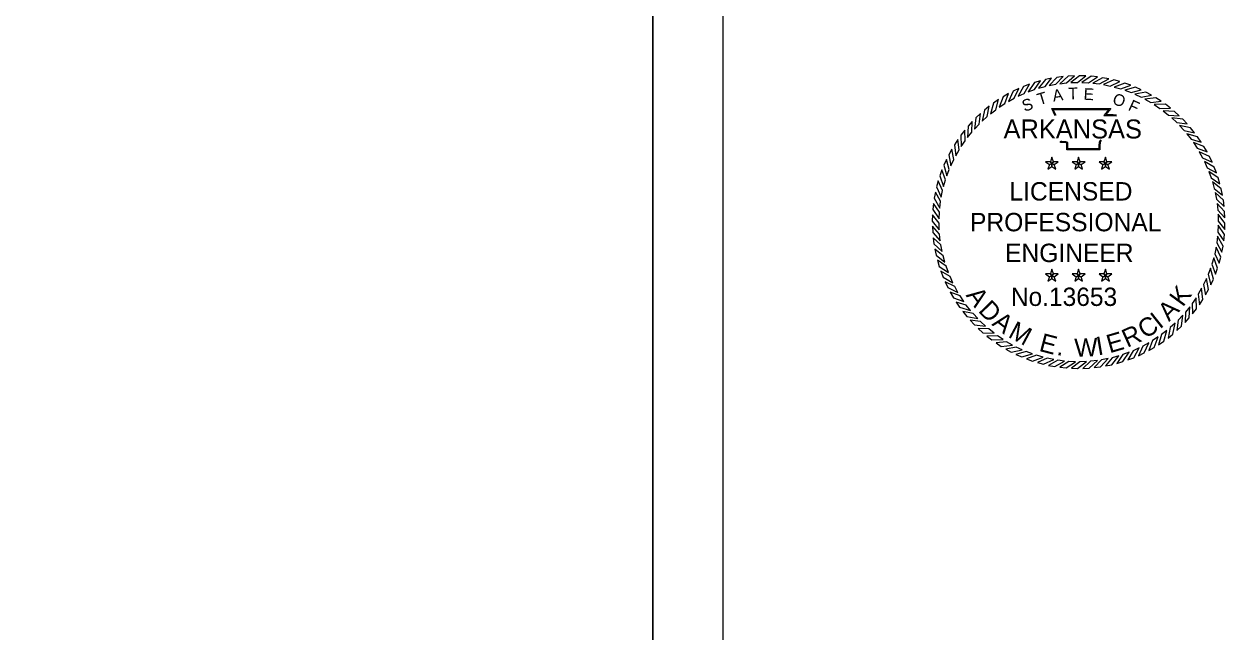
# Model space of a CAD drawing. Extents: x 0 to 38.1, y -1.4 to 22.
# Drawn here: x 28.28 to 38.1, y 10.32 to 15.29 of the extents above; entities that cross this region are included whole.
import ezdxf

# ---------------------------------------------------------------- set-up
doc = ezdxf.new("R2010")
doc.units = 0
doc.layers.add('1', color=7, linetype='Continuous')
doc.layers.add('G-ANNO-STMP-AEW', color=7, linetype='Continuous')

msp = doc.modelspace()

# ---------------------------------------------------------------- linework, layer by layer
at = {"layer": '1'}
msp.add_line((33.4232, 0.5768), (33.4232, 21.4232), dxfattribs=at)
for points in [[(34, 22), (0, 22), (0, 0), (34, 0)], [(1.516, 0.5768), (1.516, 21.4232), (25.1972, 21.4232), (25.1972, 20.4352), (29.1132, 20.4352), (29.1132, 20.1432), (33.4232, 20.1432), (33.4232, 0.5768)]]:
    msp.add_lwpolyline(points, close=True, dxfattribs=at)
at = {"layer": 'G-ANNO-STMP-AEW'}
for points in [[(36.5929, 14.8264), (36.5435, 14.8119), (36.4922, 14.7359), (36.5445, 14.7547)], [(36.6844, 14.8473), (36.6341, 14.8368), (36.577, 14.765), (36.6306, 14.7797)], [(36.7774, 14.861), (36.7263, 14.8544), (36.6638, 14.7874), (36.7184, 14.7978)], [(36.8711, 14.8674), (36.8197, 14.8648), (36.7521, 14.8029), (36.8073, 14.809)], [(36.965, 14.8664), (36.9136, 14.8679), (36.8413, 14.8114), (36.8969, 14.8132)], [(37.0586, 14.858), (37.0074, 14.8635), (36.931, 14.8129), (36.9865, 14.8103)], [(37.1512, 14.8423), (37.1006, 14.8518), (37.0204, 14.8074), (37.0756, 14.8004)], [(37.2423, 14.8194), (37.1926, 14.8329), (37.1092, 14.7949), (37.1636, 14.7836)], [(36.4161, 14.7633), (36.3696, 14.7413), (36.3308, 14.6582), (36.3795, 14.6849)], [(36.5032, 14.7983), (36.4552, 14.78), (36.41, 14.7002), (36.4607, 14.7231)], [(37.3313, 14.7895), (37.2828, 14.8067), (37.1967, 14.7754), (37.2501, 14.7599)], [(37.4177, 14.7526), (37.3707, 14.7736), (37.2824, 14.7491), (37.3344, 14.7295)], [(37.5009, 14.7091), (37.4558, 14.7337), (37.3658, 14.7162), (37.4161, 14.6926)], [(36.2513, 14.6733), (36.2088, 14.6443), (36.1836, 14.5561), (36.2275, 14.5902)], [(36.3319, 14.7216), (36.2873, 14.6959), (36.2552, 14.61), (36.3016, 14.6406)], [(37.5805, 14.6591), (37.5374, 14.6872), (37.4463, 14.6769), (37.4946, 14.6493)], [(37.6559, 14.6031), (37.6151, 14.6345), (37.5235, 14.6313), (37.5695, 14.6001)], [(36.1027, 14.5587), (36.0653, 14.5234), (36.0541, 14.4324), (36.0921, 14.4729)], [(36.1747, 14.6189), (36.1347, 14.5866), (36.1164, 14.4968), (36.1575, 14.5342)], [(37.7267, 14.5413), (37.6885, 14.5759), (37.5969, 14.5798), (37.6403, 14.5451)], [(36.0355, 14.493), (36.001, 14.4548), (35.997, 14.3632), (36.0318, 14.4066)], [(37.7924, 14.4742), (37.757, 14.5116), (37.666, 14.5228), (37.7066, 14.4847)], [(37.8526, 14.4021), (37.8203, 14.4422), (37.7305, 14.4605), (37.7679, 14.4194)], [(35.9177, 14.3468), (35.8896, 14.3037), (35.9, 14.2126), (35.9275, 14.2609)], [(35.9738, 14.4222), (35.9424, 14.3815), (35.9456, 14.2898), (35.9768, 14.3358)], [(37.907, 14.3256), (37.878, 14.368), (37.7898, 14.3933), (37.8239, 14.3494)], [(35.8678, 14.2673), (35.8432, 14.2221), (35.8607, 14.1321), (35.8843, 14.1824)], [(37.9552, 14.2449), (37.9296, 14.2896), (37.8437, 14.3217), (37.8742, 14.2752)], [(37.997, 14.1608), (37.9749, 14.2073), (37.8918, 14.246), (37.9186, 14.1973)], [(35.8243, 14.184), (35.8032, 14.1371), (35.8277, 14.0487), (35.8474, 14.1007)], [(36.6865, 14.148), (36.6742, 14.1649), (36.6345, 14.1649), (36.6667, 14.1415)], [(36.6865, 14.148), (36.6667, 14.1415), (36.6544, 14.1037), (36.6865, 14.1271)], [(36.6865, 14.148), (36.6988, 14.1649), (36.6865, 14.2027), (36.6742, 14.1649)], [(36.6865, 14.148), (36.7064, 14.1415), (36.7385, 14.1649), (36.6988, 14.1649)], [(36.6865, 14.148), (36.6865, 14.1271), (36.7187, 14.1037), (36.7064, 14.1415)], [(36.9053, 14.148), (36.893, 14.1649), (36.8533, 14.1649), (36.8854, 14.1415)], [(36.9053, 14.148), (36.8854, 14.1415), (36.8731, 14.1037), (36.9053, 14.1271)], [(36.9053, 14.148), (36.9175, 14.1649), (36.9053, 14.2027), (36.893, 14.1649)], [(36.9053, 14.148), (36.9251, 14.1415), (36.9573, 14.1649), (36.9175, 14.1649)], [(36.9053, 14.148), (36.9053, 14.1271), (36.9374, 14.1037), (36.9251, 14.1415)], [(37.124, 14.148), (37.1117, 14.1649), (37.072, 14.1649), (37.1042, 14.1415)], [(37.124, 14.148), (37.1042, 14.1415), (37.0919, 14.1037), (37.124, 14.1271)], [(37.124, 14.148), (37.1363, 14.1649), (37.124, 14.2027), (37.1117, 14.1649)], [(37.124, 14.148), (37.1439, 14.1415), (37.176, 14.1649), (37.1363, 14.1649)], [(37.124, 14.148), (37.124, 14.1271), (37.1562, 14.1037), (37.1439, 14.1415)], [(38.032, 14.0736), (38.0137, 14.1217), (37.9339, 14.1669), (37.9567, 14.1162)], [(35.7874, 14.0976), (35.7701, 14.0492), (35.8015, 13.963), (35.817, 14.0164)], [(38.0601, 13.984), (38.0456, 14.0334), (37.9695, 14.0846), (37.9884, 14.0323)], [(35.7574, 14.0086), (35.744, 13.9589), (35.782, 13.8755), (35.7933, 13.9299)], [(38.081, 13.8924), (38.0704, 13.9428), (37.9987, 13.9999), (38.0133, 13.9463)], [(35.7345, 13.9175), (35.725, 13.8669), (35.7695, 13.7868), (35.7764, 13.8419)], [(38.0947, 13.7995), (38.0881, 13.8505), (38.0211, 13.9131), (38.0315, 13.8585)], [(35.7188, 13.8249), (35.7133, 13.7737), (35.7639, 13.6973), (35.7665, 13.7528)], [(38.1011, 13.7058), (38.0985, 13.7572), (38.0366, 13.8248), (38.0427, 13.7695)], [(35.7105, 13.7313), (35.709, 13.6799), (35.7655, 13.6077), (35.7637, 13.6632)], [(38.1001, 13.6119), (38.1015, 13.6633), (38.0451, 13.7355), (38.0468, 13.68)], [(35.7095, 13.6374), (35.712, 13.586), (35.774, 13.5184), (35.7679, 13.5737)], [(38.076, 13.4257), (38.0855, 13.4762), (38.0411, 13.5564), (38.0341, 13.5013)], [(38.0917, 13.5183), (38.0972, 13.5695), (38.0466, 13.6459), (38.044, 13.5904)], [(35.7158, 13.5437), (35.7224, 13.4927), (35.7895, 13.4301), (35.7791, 13.4847)], [(35.7295, 13.4508), (35.7401, 13.4004), (35.8119, 13.3433), (35.7972, 13.3969)], [(38.0531, 13.3346), (38.0665, 13.3843), (38.0285, 13.4677), (38.0173, 13.4133)], [(35.7505, 13.3592), (35.765, 13.3098), (35.841, 13.2586), (35.8222, 13.3109)], [(38.0231, 13.2456), (38.0404, 13.294), (38.0091, 13.3802), (37.9936, 13.3268)], [(35.7786, 13.2696), (35.7969, 13.2215), (35.8767, 13.1763), (35.8538, 13.227)], [(36.6865, 13.2319), (36.6988, 13.2488), (36.6865, 13.2866), (36.6742, 13.2488)], [(36.9053, 13.2319), (36.9175, 13.2488), (36.9053, 13.2866), (36.893, 13.2488)], [(37.124, 13.2319), (37.1363, 13.2488), (37.124, 13.2866), (37.1117, 13.2488)], [(37.9863, 13.1592), (38.0073, 13.2061), (37.9828, 13.2945), (37.9632, 13.2425)], [(35.8136, 13.1824), (35.8356, 13.1359), (35.9187, 13.0972), (35.8919, 13.1459)], [(36.6865, 13.2319), (36.6742, 13.2488), (36.6345, 13.2488), (36.6667, 13.2255)], [(36.6865, 13.2319), (36.6667, 13.2255), (36.6544, 13.1877), (36.6865, 13.2111)], [(36.6865, 13.2319), (36.7064, 13.2255), (36.7385, 13.2488), (36.6988, 13.2488)], [(36.6865, 13.2319), (36.6865, 13.2111), (36.7187, 13.1877), (36.7064, 13.2255)], [(36.9053, 13.2319), (36.893, 13.2488), (36.8533, 13.2488), (36.8854, 13.2255)], [(36.9053, 13.2319), (36.8854, 13.2255), (36.8731, 13.1877), (36.9053, 13.2111)], [(36.9053, 13.2319), (36.9251, 13.2255), (36.9573, 13.2488), (36.9175, 13.2488)], [(36.9053, 13.2319), (36.9053, 13.2111), (36.9374, 13.1877), (36.9251, 13.2255)], [(37.124, 13.2319), (37.1117, 13.2488), (37.072, 13.2488), (37.1042, 13.2255)], [(37.124, 13.2319), (37.1042, 13.2255), (37.0919, 13.1877), (37.124, 13.2111)], [(37.124, 13.2319), (37.1439, 13.2255), (37.176, 13.2488), (37.1363, 13.2488)], [(37.124, 13.2319), (37.124, 13.2111), (37.1562, 13.1877), (37.1439, 13.2255)], [(37.9427, 13.0759), (37.9674, 13.1211), (37.9499, 13.2111), (37.9262, 13.1608)], [(35.8553, 13.0982), (35.8809, 13.0536), (35.9668, 13.0215), (35.9363, 13.068)], [(37.8928, 12.9964), (37.9209, 13.0395), (37.9105, 13.1306), (37.883, 13.0823)], [(35.9035, 13.0176), (35.9326, 12.9752), (36.0207, 12.9499), (35.9866, 12.9938)], [(37.775, 12.8502), (37.8095, 12.8884), (37.8135, 12.98), (37.7788, 12.9366)], [(37.8368, 12.921), (37.8682, 12.9617), (37.865, 13.0534), (37.8338, 13.0074)], [(35.9579, 12.9411), (35.9902, 12.901), (36.0801, 12.8827), (36.0427, 12.9238)], [(36.0182, 12.869), (36.0535, 12.8316), (36.1445, 12.8204), (36.104, 12.8584)], [(37.7079, 12.7845), (37.7453, 12.8198), (37.7565, 12.9108), (37.7184, 12.8703)], [(36.0839, 12.8019), (36.122, 12.7673), (36.2136, 12.7633), (36.1703, 12.7981)], [(37.5592, 12.6699), (37.6017, 12.6989), (37.627, 12.787), (37.5831, 12.753)], [(37.6358, 12.7243), (37.6759, 12.7565), (37.6941, 12.8464), (37.653, 12.809)], [(36.1547, 12.7401), (36.1954, 12.7087), (36.287, 12.7119), (36.2411, 12.7431)], [(36.2301, 12.6841), (36.2731, 12.656), (36.3642, 12.6663), (36.3159, 12.6939)], [(37.3945, 12.5799), (37.441, 12.6019), (37.4797, 12.685), (37.431, 12.6583)], [(37.4786, 12.6216), (37.5232, 12.6473), (37.5553, 12.7332), (37.5089, 12.7026)], [(36.3096, 12.6341), (36.3548, 12.6095), (36.4448, 12.627), (36.3945, 12.6506)], [(36.3928, 12.5906), (36.4398, 12.5696), (36.5282, 12.5941), (36.4762, 12.6137)], [(36.4792, 12.5537), (36.5277, 12.5364), (36.6139, 12.5678), (36.5605, 12.5833)], [(37.1261, 12.4959), (37.1764, 12.5064), (37.2335, 12.5782), (37.1799, 12.5635)], [(37.2177, 12.5168), (37.267, 12.5313), (37.3183, 12.6073), (37.266, 12.5885)], [(37.3073, 12.5449), (37.3554, 12.5632), (37.4005, 12.643), (37.3499, 12.6201)], [(36.5683, 12.5238), (36.6179, 12.5103), (36.7014, 12.5483), (36.6469, 12.5596)], [(36.6594, 12.5008), (36.7099, 12.4914), (36.7901, 12.5358), (36.735, 12.5428)], [(36.752, 12.4852), (36.8031, 12.4797), (36.8796, 12.5303), (36.8241, 12.5329)], [(36.8455, 12.4768), (36.897, 12.4753), (36.9692, 12.5318), (36.9137, 12.53)], [(36.9395, 12.4758), (36.9908, 12.4784), (37.0584, 12.5403), (37.0032, 12.5342)], [(37.0332, 12.4822), (37.0842, 12.4888), (37.1467, 12.5558), (37.0921, 12.5454)]]:
    msp.add_lwpolyline(points, close=True, dxfattribs=at)
for points in [[(36.7136, 14.5399), (36.6857, 14.6002), (37.1683, 14.6005), (37.1279, 14.5499), (37.1607, 14.5503), (37.1881, 14.5507), (37.2155, 14.5477)], [(36.7206, 14.5431), (36.6977, 14.5926), (37.1524, 14.5929), (37.1119, 14.542), (37.1608, 14.5427), (37.1877, 14.543), (37.2146, 14.5401)], [(37.0922, 14.3376), (37.084, 14.3309), (37.0813, 14.3209), (37.0785, 14.2959), (37.0785, 14.2626), (36.8092, 14.2626), (36.8092, 14.3076), (36.8092, 14.3176), (36.7982, 14.3209), (36.7599, 14.3209), (36.7531, 14.3313)], [(37.0874, 14.3436), (37.0773, 14.3353), (37.0737, 14.3224), (37.0709, 14.2963), (37.0709, 14.2702), (36.8168, 14.2702), (36.8168, 14.3076), (36.8168, 14.3233), (36.7994, 14.3286), (36.7641, 14.3286), (36.7595, 14.3355)]]:
    msp.add_lwpolyline(points, dxfattribs=at)

# ---------------------------------------------------------------- texts
for s, height, rotation, p in [('T', 0.0952, 16.90148, (36.5833, 14.6258)), ('A', 0.0952, 8.67877, (36.6989, 14.656)), ('T', 0.0952, 1.47887, (36.8218, 14.675)), ('E', 0.0952, 356.67203, (36.9436, 14.6721)), ('S', 0.0952, 19.77256, (36.4623, 14.5715)), ('O', 0.0952, 341.2218, (37.1747, 14.6394)), ('F', 0.0952, 335.36282, (37.303, 14.5893)), ('K', 0.1504, 53.84706, (37.7571, 12.9717)), ('A', 0.1504, 305.982, (35.9797, 13.0729)), ('D', 0.1504, 314.30216, (36.0784, 12.9429)), ('A', 0.1504, 45.18496, (37.6443, 12.8537)), ('A', 0.1504, 322.62232, (36.1899, 12.8329)), ('C', 0.1504, 32.13964, (37.449, 12.7133)), ('I', 0.1504, 38.40573, (37.5684, 12.7926)), ('M', 0.1504, 331.79687, (36.3212, 12.7358)), ('E', 0.1504, 16.01252, (37.1582, 12.599)), ('R', 0.1504, 24.16163, (37.3017, 12.643)), ('E', 0.1504, 345.2782, (36.5746, 12.6204)), ('W', 0.1504, 2.1127, (36.8734, 12.5689)), ('I', 0.1504, 9.57533, (37.0624, 12.5818)), ('.', 0.1504, 350.85832, (36.7206, 12.5864))]:
    msp.add_text(s, height=height, rotation=rotation, dxfattribs=at).set_placement(p)
for s, height, p in [('ARKANSAS', 0.15535, (36.2913, 14.355)), ('LICENSED', 0.15039, (36.3395, 13.8479)), ('PROFESSIONAL', 0.150392, (36.0172, 13.5964)), ('ENGINEER', 0.15039, (36.3037, 13.3449)), ('No.13653', 0.1498, (36.3512, 12.9864))]:
    msp.add_text(s, height=height, dxfattribs=at).set_placement(p)

doc.saveas('drawing.dxf')
